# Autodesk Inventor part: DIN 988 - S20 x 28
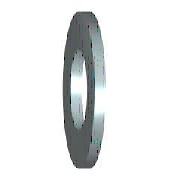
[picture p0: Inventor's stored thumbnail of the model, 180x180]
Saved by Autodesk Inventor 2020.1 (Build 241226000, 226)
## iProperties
Manager: www.cadconsulting.pl
Company: Fabian Stasiak CAD Consulting
Created: 2006-02
Part Number: DIN 988 - S20 x 28
Material: Stal, miękka
Description: Pierścień
Document SubType Name: Modeling
Standard: DIN 988
Designer: F.Stasiak
Standards Organization: DIN
Language: pl-PL
Size Designation: S20 x 28
Categories: <MemberInstance><Categories><Category DisplayName="Mocowania" InternalName="e4da775c-781d-43d5-af7c-5136215cf5a6" Mnemonic="FSTN"><Category DisplayName="Podkład
Density: 7.85 g/cm^3
Appearance: Stal
Mass: 4.73501 g
Surface Area: 9.04779 cm^2
Volume: 0.603186 cm^3
Author: F.Stasiak
Subject: Zbiór ćwiczeń. Autodesk Inventor 2020. Kurs podstawowy
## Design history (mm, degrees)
sketch "Szkic"
  geometry: C1 r 14 at (0, 0); C2 r 10 at (0, 0); 1 further point
  constraints: 2 centre point, 2 coincident
  dimensions: "d0" = 20 diameter of C2 (= SD1); "d1" = 28 diameter of C1 (= SD2)
extrude "Bryła" new body sketch "Szkic" distance "d2" = 2 (= SD); taper "d3" = 0 deg
workaxis "Work Axis1"
workplane "Work Plane1"
node "Bryła1"
node "Korpusy bryłowe"
node "Korpusy powierzchniowe"
other parameters: "SD1" = 20 [user parameter; used in 1 equation term], "SD2" = 28 [user parameter; used in 1 equation term], "SD" = 2 [user parameter; used in 1 equation term], "d4" = 0, "d5" = 0, "d6" = 0, "d7" = 0
